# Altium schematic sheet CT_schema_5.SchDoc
size 258 x 142 mm
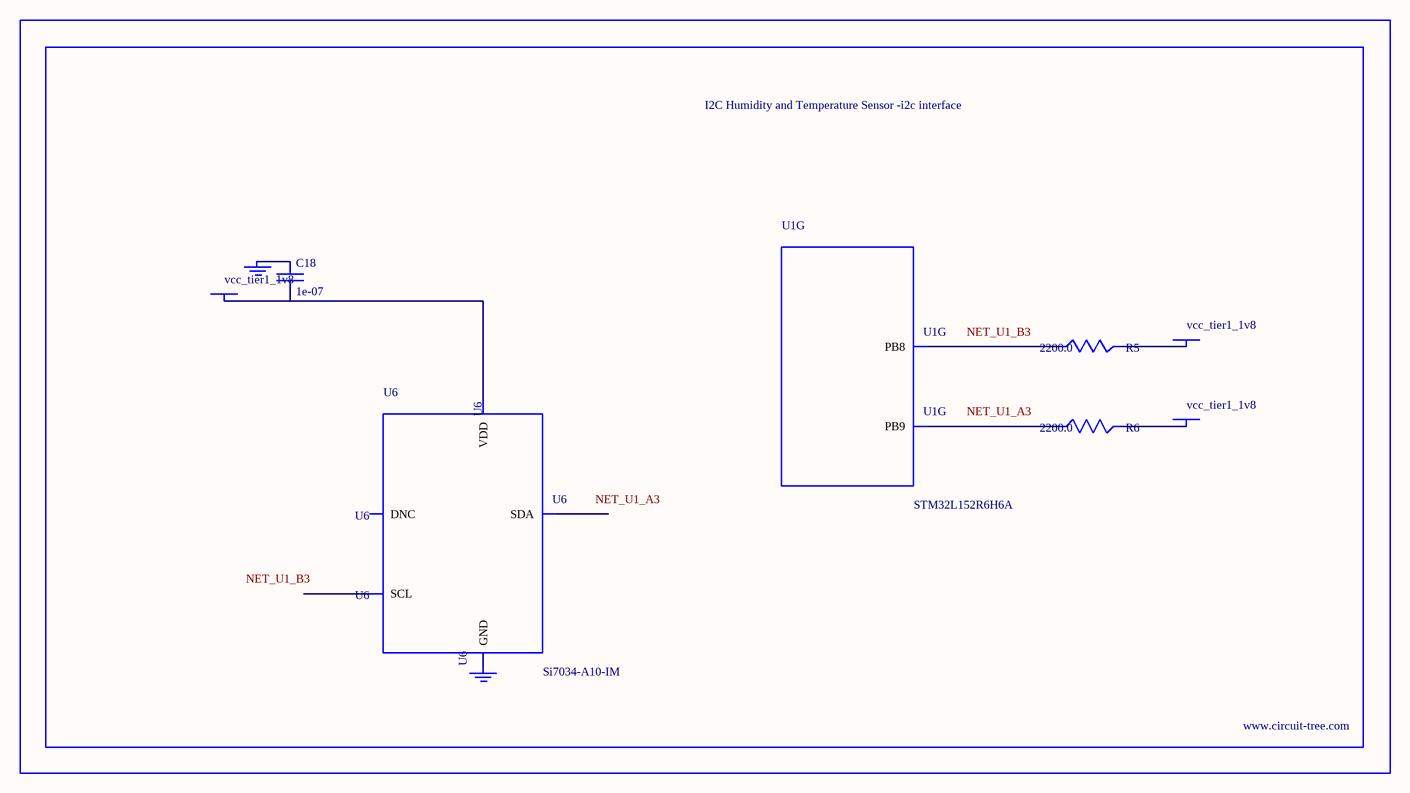
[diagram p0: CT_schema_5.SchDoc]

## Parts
BORDER4  (no value)
C18  1e-07  [C0402]
GND_INSTANCE_4_0  (no value)
GND_INSTANCE_4_1  (no value)
POWER_INSTANCE_4_0  vcc_tier1_1v8
POWER_INSTANCE_4_1  vcc_tier1_1v8
POWER_INSTANCE_4_2  vcc_tier1_1v8
R5  2200.0  [R0603]
R6  2200.0  [R0603]
U1  STM32L152R6H6A  [TFBGA64]  (part G of 7)
U6  Si7034-A10-IM  [SI7034-A10-IM]

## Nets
NetC18_1: C18.1 GND_INSTANCE_4_0.0(GND)
NetC18_2: C18.2 POWER_INSTANCE_4_0.0(PWR) U6.1(VDD)
NetGND_INSTANCE_4_1_0: GND_INSTANCE_4_1.0(GND) U6.5(GND)
NetPOWER_INSTANCE_4_1_0: POWER_INSTANCE_4_1.0(PWR) R5.2
NetPOWER_INSTANCE_4_2_0: POWER_INSTANCE_4_2.0(PWR) R6.2
NetR5_1: R5.1 U1.B3(PB8)
NetR6_1: R6.1 U1.A3(PB9)

Not connected (* = marked no-connect by the designer): U6 2(SCL) 3(DNC) 4(SDA)

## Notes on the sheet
- Labels drawn without touching a wire or pin: NET_U1_A3, NET_U1_B3

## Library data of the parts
BORDER4 = BORDER_PAGE4
C18 = C0402C104K3RACTU
GND_INSTANCE_4_0 GND_INSTANCE_4_1 = GND
POWER_INSTANCE_4_0-POWER_INSTANCE_4_2 = PWR
R5 R6 = RC0603JR-072K2L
